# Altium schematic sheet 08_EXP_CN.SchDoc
size A2; ApprovedBy: DNP; CheckedBy: DNP; Author: DNP; CompanyName: Google LLC; DrawnBy: DNP; Engineer: Bangfei/Michael/Leo; Organization: Google LLC; Address1: 1600 Amphitheatre Parkway; Address2: Mountain View, CA 94043; Address3: DNP; Address4: DNP; DocumentNumber: DNP; Revision: PVT; SheetNumber: 8; SheetTotal: 11; VersionControl_RevNumber: DNP; IsUserConfigurable: DNP
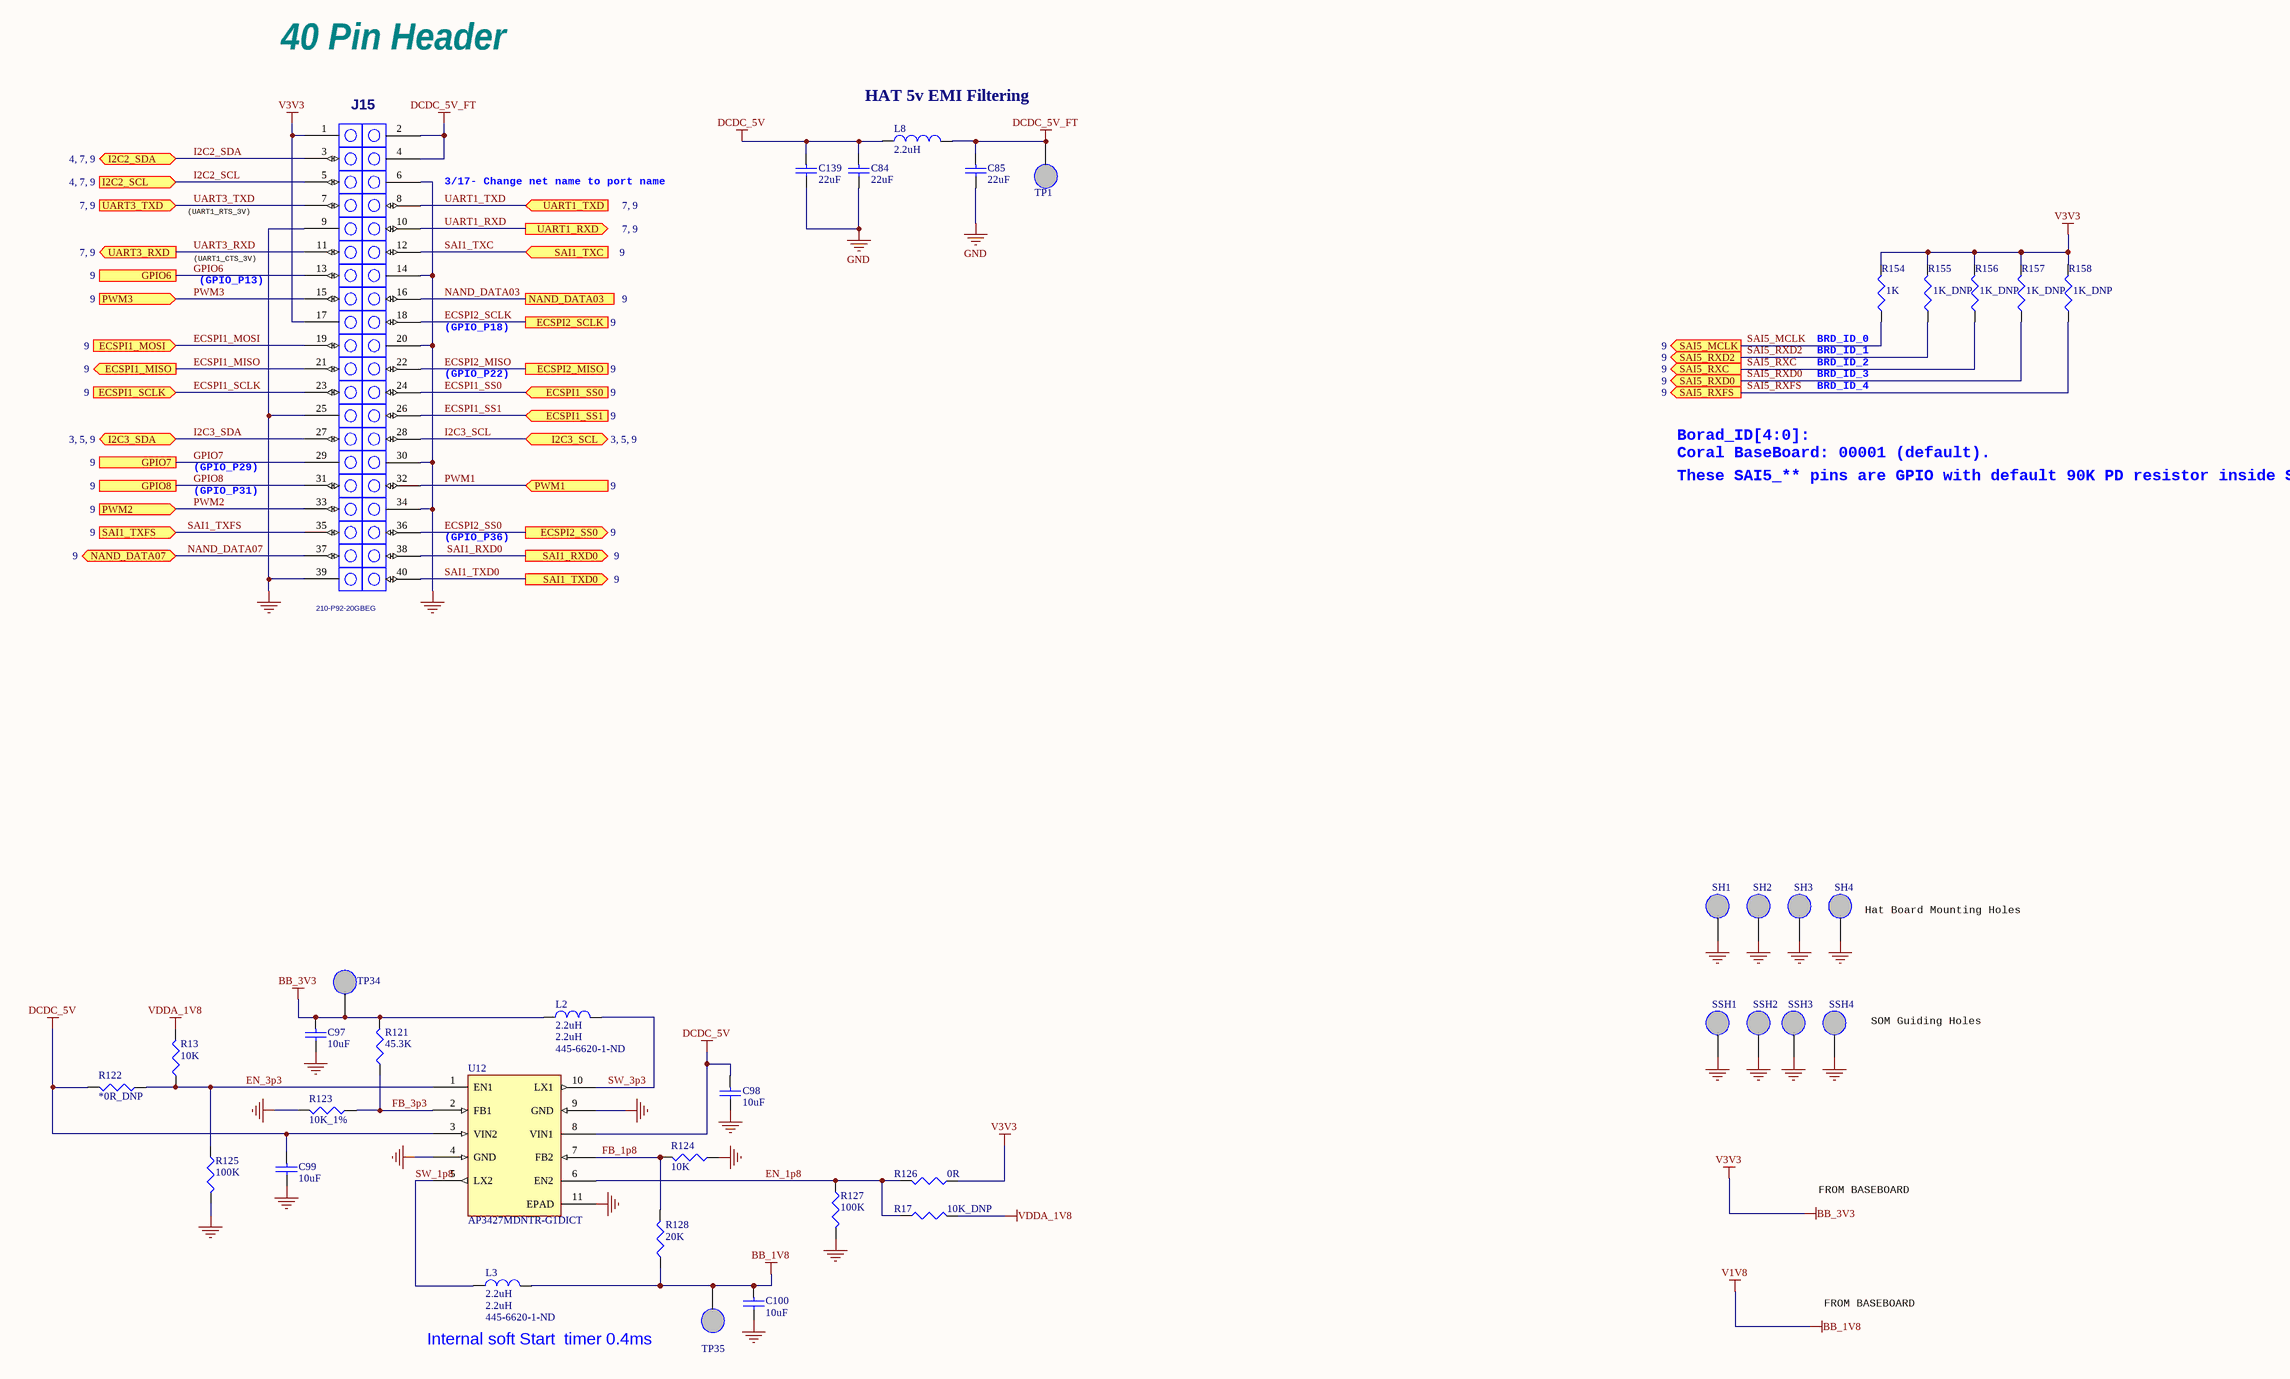
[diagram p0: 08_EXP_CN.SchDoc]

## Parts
C84  value 22uF  [0603]  (hidden comment: 22uF/10V)
C85  value 22uF  [0603]  (hidden comment: 22uF/10V)
C97  value 10uF  [0402]  (hidden comment: 10uF/10V)
C98  value 10uF  [0402]  (hidden comment: 10uF/10V)
C99  value 10uF  [0402]  (hidden comment: 10uF/10V)
C100  value 10uF  [0402]  (hidden comment: 10uF/10V)
C139  value 22uF  [0603]  (hidden comment: 22uF/10V)
J15  210-P92-20GBEG  [HTSW-120-41-G-D]
L2  2.2uH  Supplier Part Number 1: 445-6620-1-ND  [INDC2016X12L]
L3  2.2uH  Supplier Part Number 1: 445-6620-1-ND  [INDC2016X12L]
L8  2.2uH  [0805_PADS]
R13  value 10K  [0201]  (hidden comment: 10K_DNP)
R17  10K_DNP  [0201]
R121  45.3K  [0201]
R122  value *0R_DNP  [0201]  (hidden comment: 0R)
R123  value 10K_1%  [0201]  (hidden comment: 10K)
R124  10K  [0201]
R125  100K  [0201]
R126  0R  [0201]
R127  100K  [0201]
R128  20K  [0201]
R154  value 1K  [0201]  (hidden comment: 1K/1%)
R155  1K_DNP  [0201]
R156  1K_DNP  [0201]
R157  1K_DNP  [0201]
R158  1K_DNP  [0201]
SH1  TP NM  [hole236-110]  (value not drawn)  (no BOM)
SH2  TP NM  [hole236-110]  (value not drawn)  (no BOM)
SH3  TP NM  [hole236-110]  (value not drawn)  (no BOM)
SH4  TP NM  [hole236-110]  (value not drawn)  (no BOM)
SSH1  stand-off  [hole120-80]  (value not drawn)  (no BOM)
SSH2  stand-off  [hole120-80]  (value not drawn)  (no BOM)
SSH3  stand-off  [hole120-80]  (value not drawn)  (no BOM)
SSH4  stand-off  [hole120-80]  (value not drawn)  (no BOM)
TP1  TP NM  [TP_SMD]  (value not drawn)  (no BOM)
TP34  TP NM  [TP_SMD_L]  (value not drawn)  (no BOM)
TP35  TP NM  [TP_SMD_L]  (value not drawn)  (no BOM)
U12  AP3427MDNTR-G1DICT  [DFN_10_3X3]

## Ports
ECSPI1_MISO (out, see 9), ECSPI1_MOSI (in, see 9), ECSPI1_SCLK (in, see 9), ECSPI1_SS0 (in, see 9), ECSPI1_SS1 (in, see 9), ECSPI2_MISO (see 9), ECSPI2_SCLK (see 9), ECSPI2_SS0 (out, see 9), GPIO6 (see 9), GPIO7 (see 9), GPIO8 (see 9), I2C2_SCL (in, see 4, 7, 9), I2C2_SDA (bidir, see 4, 7, 9), I2C3_SCL (bidir, see 3, 5, 9), I2C3_SDA (bidir, see 3, 5, 9), NAND_DATA03 (see 9), NAND_DATA07 (bidir, see 9), PWM1 (in, see 9), PWM2 (in, see 9), PWM3 (in, see 9), SAI1_RXD0 (out, see 9), SAI1_TXC (in, see 9), SAI1_TXD0 (out, see 9), SAI1_TXFS (in, see 9), SAI5_MCLK (out, see 9), SAI5_RXC (out, see 9), SAI5_RXD0 (out, see 9), SAI5_RXD2 (out, see 9), SAI5_RXFS (out, see 9), UART1_RXD (out, see 7, 9), UART1_TXD (in, see 7, 9), UART3_RXD (out, see 7, 9), UART3_TXD (in, see 7, 9)

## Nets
BB_1V8: C100.1 L3.2 R128.1 TP35.1  [also labelled V1V8]
BB_3V3: C97.1 J15.1 J15.17 L2.1 R121.2 R126.1 R154.2 R155.2 R156.2 R157.2 R158.2 TP34.1  [also labelled V3V3]
DCDC_5V: C84.1 C98.1 C99.1 C139.1 L8.1 R122.2 U12.3(VIN2) U12.8(VIN1)
DCDC_5V_FT: C85.1 J15.2 J15.4 L8.2 TP1.1
GND: C84.2 C85.2 C97.2 C98.2 C99.2 C100.2 C139.2 J15.6 J15.9 J15.14 J15.20 J15.25 J15.30 J15.34 J15.39 R123.2 R124.1 R125.2 R127.2 SH1.1 SH2.1 SH3.1 SH4.1 SSH1.1 SSH2.1 SSH3.1 SSH4.1 U12.4(GND) U12.9(GND) U12.11(EPAD)
VDDA_1V8: R13.2 R17.2
ECSPI1_MISO: J15.21 ; port ECSPI1_MISO
ECSPI1_MOSI: J15.19 ; port ECSPI1_MOSI
ECSPI1_SCLK: J15.23 ; port ECSPI1_SCLK
ECSPI1_SS0: J15.24 ; port ECSPI1_SS0
ECSPI1_SS1: J15.26 ; port ECSPI1_SS1
ECSPI2_MISO: J15.22 ; port ECSPI2_MISO
ECSPI2_SCLK: J15.18 ; port ECSPI2_SCLK
ECSPI2_SS0: J15.36 ; port ECSPI2_SS0
EN_1p8: R17.1 R126.2 R127.1 U12.6(EN2)
EN_3p3: R13.1 R122.1 R125.1 U12.1(EN1)
FB_1p8: R124.2 R128.2 U12.7(FB2)
FB_3p3: R121.1 R123.1 U12.2(FB1)
GPIO6: J15.13 ; port GPIO6
GPIO7: J15.29 ; port GPIO7
GPIO8: J15.31 ; port GPIO8
I2C2_SCL: J15.5 ; port I2C2_SCL
I2C2_SDA: J15.3 ; port I2C2_SDA
I2C3_SCL: J15.28 ; port I2C3_SCL
I2C3_SDA: J15.27 ; port I2C3_SDA
NAND_DATA03: J15.16 ; port NAND_DATA03
NAND_DATA07: J15.37 ; port NAND_DATA07
PWM1: J15.32 ; port PWM1
PWM2: J15.33 ; port PWM2
PWM3: J15.15 ; port PWM3
SAI1_RXD0: J15.38 ; port SAI1_RXD0
SAI1_TXC: J15.12 ; port SAI1_TXC
SAI1_TXD0: J15.40 ; port SAI1_TXD0
SAI1_TXFS: J15.35 ; port SAI1_TXFS
SAI5_MCLK: R154.1 ; port SAI5_MCLK
SAI5_RXC: R156.1 ; port SAI5_RXC
SAI5_RXD0: R157.1 ; port SAI5_RXD0
SAI5_RXD2: R155.1 ; port SAI5_RXD2
SAI5_RXFS: R158.1 ; port SAI5_RXFS
SW_1p8: L3.1 U12.5(LX2)
SW_3p3: L2.2 U12.10(LX1)
UART1_RXD: J15.10 ; port UART1_RXD
UART1_TXD: J15.8 ; port UART1_TXD
UART3_RXD: J15.11 ; port UART3_RXD
UART3_TXD: J15.7 ; port UART3_TXD

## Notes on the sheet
- 40 Pin Header
- (near L8) HAT 5v EMI Filtering
- 3/17- Change net name to port name
- (UART1_RTS_3V)
- (UART1_CTS_3V)
- (GPIO_P13)
- (GPIO_P18)
- (near R154) BRD_ID_0
- (near R154) BRD_ID_1
- BRD_ID_2
- (GPIO_P22)
- BRD_ID_3
- BRD_ID_4
- (GPIO_P29)
- Borad_ID[4:0]:
- These SAI5_** pins are GPIO with default 90K PD resistor inside SOC.
- Coral BaseBoard: 00001 (default).
- (GPIO_P31)
- (GPIO_P36)
- (near SH4) Hat Board Mounting Holes
- (near SSH4) SOM Guiding Holes
- FROM BASEBOARD
- (near TP35) Internal soft Start  timer 0.4ms

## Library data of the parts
C84 C139 = CAP_0603_22uF: CAP CER 22UF 6.3V 10% X5R 0603; MPN: CL10A226KQ8NRNE; QCI MPN: GRM188R61A226M; QPN: CH6222M9901; QPN Description: CAP CHIP 22UF 10V(+-20%,X5R,0603); Function Code: USB
C85 = CAP_0603_22uF: CAP CER 22UF 6.3V 10% X5R 0603; MPN: CL10A226KQ8NRNE; QCI MPN: GRM188R61A226M; QPN: CH6222M9901; QPN Description: CAP CHIP 22UF 10V(+-20%,X5R,0603); Function Code: DOK
C97-C100 = CAP_0402_10uF: CAP CER 10UF 10V 20% X5R 0402; MPN: CL05A106MP5NUNC; QCI MPN: GRM155R61A106M; QPN: CH6102M9B00; QPN Description: CAP CHIP 10U 10V (+-20%, X5R, 0402)'; Function Code: DCD
J15 = CONN_HEADER_20x2_SMT: SOCKET 2X20 100-MIL STRAIGHT SMT; Function Code: DOK; QPN: DFHD20MS161; QPN Description: CONN DIP HEADER 20P 2R MS(P2.54,H8.3)
L2 L3 = INDUCTOR_VLS201612ET-2R2M: FIXED IND 2.2UH 1.05A 195 MOHM SMD; QPN: CV-2210MZ02; QPN Description: IND SMD2.2UH+-20%1.05A(VLS201612ET-2R2M); Function Code: DCD
L8 = INDUCTOR_2.2uH_800mA_0805: 2.2?Inductor 800mA 200 mOhm Max 0805 (2012 Metric); MPN: SDTR20120H-2R2MS; QPN: CV-2213MZ14; Function Code: DOK; QPN Description: IND SMD 2.2UH +-20%1.3A SDTR20120H-2R2MS
R13 R17 = R_0201_10K: RES SMD 10K OHM JUMPER 1/20W  0201; MPN: ERJ-1GEF103C; QCI MPN: RC0201JR-1310KL; DNP: V; QPN: CS31001JE16; QPN Description: RES CHIP 10K 1/20W +-5%(0201); Function Code: DCD
R121 = R_0201_453K: RES CHIP 45.3K 1/20W +-1%(0201); MPN: RM02FTN4532; QPN: CS34531FE01; Function Code: DCD
R122 R126 = R_0201_0: RES SMD 0.0OHM JUMPER 1/20W 0201; MPN: ERJ-1GN0R00C; QCI MPN: RC0201JR-130RL; QPN: CS00001JE18; QPN Description: RES CHIP 0(1/20W,+-5%,0201); Function Code: DCD
R123 = R_0201_10K: RES SMD 10K OHM JUMPER 1/20W  0201; MPN: ERJ-1GEF103C; QCI MPN: RC0201JR-1310KL; QPN: CS31001FE14; QPN Description: RES CHIP 10K 1/20W +-1%(0201); Function Code: DCD
R124 = R_0201_10K: RES SMD 10K OHM JUMPER 1/20W  0201; MPN: ERJ-1GEF103C; QCI MPN: RC0201JR-1310KL; QPN: CS31001JE16; QPN Description: RES CHIP 10K 1/20W +-5%(0201); Function Code: DCD
R125 R127 = R_0201_100K: RES SMD 100K OHM JUMPER 1/20W  0201; MPN: ERJ-1GEF1003C; QCI MPN: RC0201FR-07100KL; QPN: TS41001FE04; QPN Description: RES CHIP 100K 1/20W +-1%(0201)EMS-SEL; Function Code: DCD
R128 = R_0201_20K: RES SMD 20K OHM 1% 1/20W 0201; MPN: ERJ-1GEF2002C; QCI MPN: RC0201FR-0720KL; QPN: CS32001FE00; QPN Description: RES CHIP 20K 1/20W +-1%(0201); Function Code: DCD
R154 = R_0201_1K: RES SMD 1K OHM 1% 1/20W 0201; MPN: ERJ-1GEF1001C; QCI MPN: RC0201FR-131KL; QPN: CS21001FE04; QPN Description: RES CHIP 1K 1/20W +-1%(0201); Function Code: DOK
R155-R158 = R_0201_1K: RES SMD 1K OHM 1% 1/20W 0201; MPN: ERJ-1GEF1001C; QCI MPN: RC0201FR-131KL; DNP: V; QPN: CS21001FE04; QPN Description: RES CHIP 1K 1/20W +-1%(0201); Function Code: DOK
SH1-SH4 TP1 = TP: TEST POIN
SSH1-SSH4 = TP: QCI MPN: 1000401131
TP34 TP35 = TP_L: TEST POINT (Large)
U12 = AP3427M: Dual 1A, 1.5NMhz, Sync Step-Down DC/DC Converter; QPN: LL003427000; QPN Description: IC OTHER(10P)AP3427MDNTR(DFN3030)ESEL; Function Code: DCD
